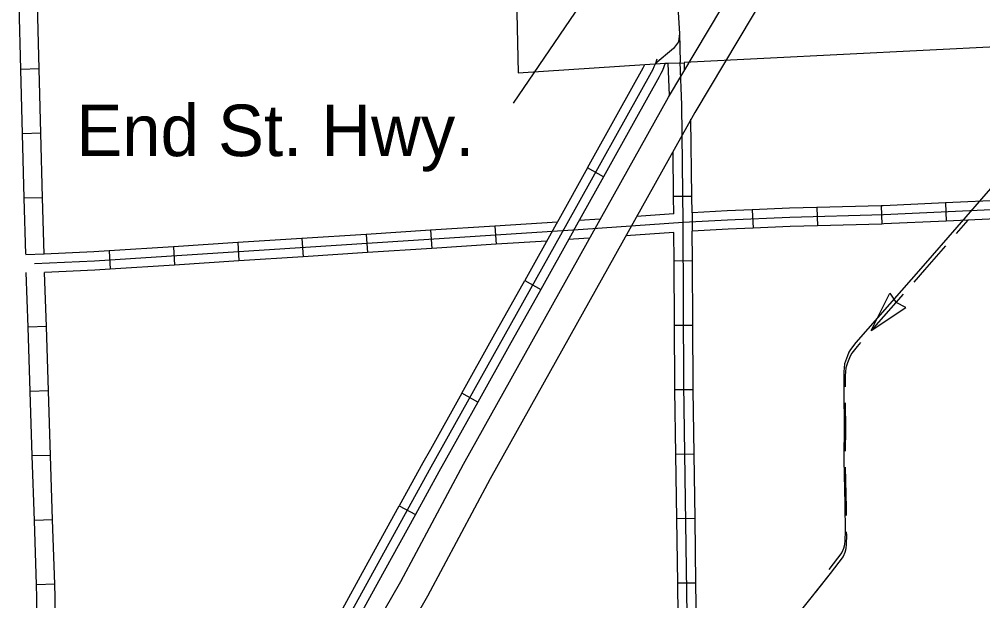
# Model space of a CAD drawing. Extents: x 1164457 to 1439835, y 1590918 to 1773502.
# Drawn here: x 1250867 to 1258762, y 1619648 to 1624411 of the extents above; entities that cross this region are included whole.
import ezdxf

# ---------------------------------------------------------------- set-up
doc = ezdxf.new("R2010")
doc.units = 0
for name, color, linetype in [('Level 15', 7, 'Continuous'), ('Level 31', 7, 'Continuous'), ('Level 32', 7, 'Continuous'), ('Level 33', 7, 'Continuous'), ('Level 34', 7, 'Continuous'), ('Level 41', 7, 'Continuous'), ('Level 43', 7, 'Continuous'), ('Level 6', 7, 'Continuous')]:
    doc.layers.add(name, color=color, linetype=linetype)

msp = doc.modelspace()

# ---------------------------------------------------------------- linework, layer by layer
at = {"layer": 'Level 15'}
for points in [[(1253993.2, 1619805.1), (1254506.1, 1620766.5), (1256186.5, 1623773.6), (1257379.6, 1625774), (1258934.5, 1628282.8), (1259494.9, 1629192.9), (1260659.4, 1631068)], [(1260872.2, 1630936.8), (1259707.6, 1629061.4), (1259147.2, 1628151.4), (1257593.2, 1625644.1), (1256403.1, 1623648.5), (1254725.5, 1620646.6), (1254211.9, 1619684)], [(1251163.5, 1614663.9), (1251218.9, 1614766.1), (1251254.2, 1614833.3), (1251300.8, 1614938.9), (1251428, 1615195.4), (1252210.7, 1616646.9), (1252911.7, 1617922.8), (1253993.2, 1619805.1)], [(1254211.9, 1619684), (1253129.6, 1617800.3), (1252430.3, 1616527.4), (1251647.9, 1615076.4), (1251506.8, 1614816.2), (1251450.7, 1614714.5), (1251414.8, 1614638.1), (1251385.8, 1614586.3), (1251323.1, 1614487.1), (1251311.8, 1614470.8)]]:
    msp.add_lwpolyline(points, dxfattribs=at)
at = {"layer": 'Level 31'}
for p, q in [((1255653.9, 1623120.3), (1255522.9, 1623193.2)), ((1255008.7, 1622270.9), (1255139.7, 1622197.8)), ((1254625, 1621275.7), (1254494, 1621348.9)), ((1254494, 1621348.9), (1254494, 1621348.9)), ((1253981, 1620425.4), (1254112.4, 1620353))]:
    msp.add_line(p, q, dxfattribs=at)
for points in [[(1256090, 1624084.8), (1256087.5, 1624075.1), (1256079, 1624048.3), (1256067.9, 1624021.3), (1256057.9, 1624000.3), (1256044.3, 1623975.8), (1255353.8, 1622735.2), (1254240.6, 1620741), (1252203.6, 1617045.1)], [(1255779.6, 1623654.6), (1255978.7, 1624012.2), (1255994.3, 1624040.3), (1256158.6, 1624051.1)], [(1256158.6, 1624051.1), (1256149.6, 1624022.7), (1256136.4, 1623990.8), (1256124.6, 1623965.9), (1256109.8, 1623939.4), (1255910.7, 1623581.6)], [(1255522.9, 1623193.2), (1255779.6, 1623654.6)], [(1255910.7, 1623581.6), (1255653.9, 1623120.3)], [(1255522.9, 1623193.2), (1255288.3, 1622771.7), (1255266.1, 1622732)], [(1255653.9, 1623120.3), (1255419.3, 1622698.7), (1255397.1, 1622658.8)], [(1255266.1, 1622732), (1255008.7, 1622270.9)], [(1255397.1, 1622658.8), (1255139.7, 1622197.8)], [(1254751.4, 1621809.9), (1255008.7, 1622270.9)], [(1255139.7, 1622197.8), (1254882.4, 1621736.8)], [(1254494, 1621348.9), (1254751.4, 1621809.9)], [(1254882.4, 1621736.8), (1254625, 1621275.7)], [(1254494, 1621348.9), (1254236.7, 1620887.8)], [(1254625, 1621275.7), (1254367.7, 1620814.7)], [(1254236.7, 1620887.8), (1254175.1, 1620777.4), (1253981, 1620425.4)], [(1254367.7, 1620814.7), (1254306.2, 1620704.7), (1254112.4, 1620353)], [(1253726.2, 1619963), (1253981, 1620425.4)], [(1254112.4, 1620353), (1253857.5, 1619890.6)], [(1253471.3, 1619500.5), (1253726.2, 1619963)], [(1253857.5, 1619890.6), (1253602.7, 1619428.1)]]:
    msp.add_lwpolyline(points, dxfattribs=at)
at = {"layer": 'Level 32'}
for p, q in [((1251030.5, 1624005), (1250880.5, 1624001.1)), ((1251044.2, 1623477.2), (1250894.2, 1623473.3)), ((1251057.9, 1622949.4), (1250907.9, 1622945.5)), ((1256378.7, 1622960.2), (1256228.8, 1622958.4)), ((1258456.4, 1622907.2), (1258463.2, 1622757.3)), ((1256380.3, 1622825.3), (1256381.7, 1622675.2)), ((1256873.7, 1622849.9), (1256880.2, 1622700.1)), ((1257402.5, 1622869.3), (1257406.6, 1622719.3)), ((1257930.3, 1622883.7), (1257934.4, 1622733.7)), ((1254237.4, 1622683.3), (1254247.1, 1622533.6)), ((1254764.3, 1622717.3), (1254774, 1622567.6)), ((1253183.6, 1622615.3), (1253193.3, 1622465.7)), ((1253710.5, 1622649.3), (1253720.2, 1622499.7)), ((1251602.9, 1622513.4), (1251612.6, 1622363.7)), ((1252129.8, 1622547.4), (1252139.5, 1622397.7)), ((1252656.7, 1622581.4), (1252666.4, 1622431.7)), ((1251069.9, 1622487.1), (1250919.9, 1622482.2)), ((1256383, 1622431.8), (1256233, 1622430.9)), ((1251088.8, 1621894.3), (1250938.9, 1621889.4)), ((1256386, 1621903.8), (1256236, 1621903)), ((1251106, 1621366.6), (1250956.1, 1621361.7)), ((1256389.3, 1621376.5), (1256239.3, 1621374.3)), ((1256396.9, 1620848.5), (1256246.9, 1620846.4)), ((1251123.2, 1620838.9), (1250973.3, 1620834)), ((1251140.4, 1620311.2), (1250990.5, 1620306.3)), ((1256404.5, 1620320.6), (1256254.5, 1620318.4)), ((1251157.6, 1619783.4), (1251007.7, 1619778.5)), ((1256412.1, 1619792.6), (1256262.2, 1619790.5))]:
    msp.add_line(p, q, dxfattribs=at)
for points in [[(1261295.4, 1630547.9), (1261306.2, 1630051), (1261324.9, 1629664.4), (1261348.7, 1628964), (1261365.2, 1628368), (1261458.8, 1624497.4), (1261503, 1623132.1), (1261505.5, 1623067.7), (1261501.7, 1623041.2), (1261495.4, 1623009.6), (1261481.5, 1622985.6), (1261466, 1622969.5), (1261449.4, 1622961.7), (1261391.9, 1622953.3), (1261142.6, 1622941.1), (1260938.5, 1622942), (1258950.1, 1622854.5), (1257949.9, 1622809.2), (1257180.1, 1622788.2), (1256671, 1622766), (1256306.3, 1622746.2), (1255487.8, 1622688.9), (1251482.4, 1622430.4), (1250992.3, 1622408.6)], [(1250880.5, 1624001.1), (1250866.8, 1624528.9)], [(1251030.5, 1624005), (1251016.8, 1624532.8)], [(1256194.7, 1623787.2), (1256184.5, 1624051.7), (1256316.7, 1624055.8)], [(1256372.7, 1617457.4), (1256353.6, 1618242.9), (1256357.3, 1618398.2), (1256313.6, 1621419), (1256306.3, 1622746.2), (1256294.8, 1623711), (1256281.4, 1624058.9)], [(1256317.4, 1623993), (1256316.7, 1624055.8)], [(1250894.2, 1623473.3), (1250880.5, 1624001.1)], [(1251044.2, 1623477.2), (1251030.5, 1624005)], [(1256378.7, 1622960.2), (1256371.2, 1623591.6)], [(1250907.9, 1622945.5), (1250894.2, 1623473.3)], [(1251057.9, 1622949.4), (1251044.2, 1623477.2)], [(1256228.8, 1622958.4), (1256224.3, 1623328.7)], [(1250919.8, 1622487), (1250907.9, 1622945.5)], [(1251069.9, 1622487.1), (1251057.9, 1622949.4)], [(1256230.4, 1622816.1), (1256228.8, 1622958.4)], [(1256380.3, 1622825.3), (1256378.7, 1622960.2)], [(1258456.4, 1622907.2), (1257947.1, 1622884.1), (1257930.3, 1622883.7)], [(1258984, 1622931), (1258946.7, 1622929.4), (1258456.4, 1622907.2)], [(1256873.7, 1622849.9), (1256667.3, 1622840.9), (1256380.3, 1622825.3)], [(1257402.5, 1622869.3), (1257177.4, 1622863.2), (1256873.7, 1622849.9)], [(1257930.3, 1622883.7), (1257402.5, 1622869.3)], [(1255276.4, 1622750.4), (1254764.3, 1622717.3)], [(1255627.9, 1622773.9), (1255454.4, 1622761.7)], [(1256230.4, 1622816.1), (1255925.9, 1622794.7)], [(1258463.2, 1622757.3), (1257952.6, 1622734.2), (1257934.4, 1622733.7)], [(1258876, 1622776), (1258463.2, 1622757.3)], [(1254237.4, 1622683.3), (1253710.5, 1622649.3)], [(1254764.3, 1622717.3), (1254237.4, 1622683.3)], [(1256231.7, 1622665.8), (1255838.5, 1622638.2)], [(1256233, 1622430.9), (1256231.7, 1622665.8)], [(1256880.2, 1622700.1), (1256674.7, 1622691.1), (1256381.7, 1622675.2)], [(1256383, 1622431.8), (1256381.7, 1622675.2)], [(1257406.6, 1622719.3), (1257182.7, 1622713.2), (1256880.2, 1622700.1)], [(1257934.4, 1622733.7), (1257406.6, 1622719.3)], [(1253183.6, 1622615.3), (1252656.7, 1622581.4)], [(1253710.5, 1622649.3), (1253183.6, 1622615.3)], [(1255189.3, 1622594.4), (1254774, 1622567.6)], [(1255540.4, 1622617.4), (1255492.9, 1622614), (1255367.5, 1622605.9)], [(1251602.9, 1622513.4), (1251478.3, 1622505.3), (1251069.9, 1622487.1)], [(1252129.8, 1622547.4), (1251602.9, 1622513.4)], [(1252656.7, 1622581.4), (1252129.8, 1622547.4)], [(1254247.1, 1622533.6), (1253720.2, 1622499.7)], [(1254774, 1622567.6), (1254247.1, 1622533.6)], [(1252666.4, 1622431.7), (1252139.5, 1622397.7)], [(1253193.3, 1622465.7), (1252666.4, 1622431.7)], [(1253720.2, 1622499.7), (1253193.3, 1622465.7)], [(1256236, 1621903), (1256233, 1622430.9)], [(1256386, 1621903.8), (1256383, 1622431.8)], [(1251612.6, 1622363.7), (1251486.4, 1622355.5), (1251074.3, 1622337.2)], [(1252139.5, 1622397.7), (1251612.6, 1622363.7)], [(1250938.9, 1621889.4), (1250924.3, 1622337)], [(1251088.8, 1621894.3), (1251074.3, 1622337.2)], [(1250956.1, 1621361.7), (1250938.9, 1621889.4)], [(1251106, 1621366.6), (1251088.8, 1621894.3)], [(1256239.3, 1621374.3), (1256238.7, 1621418.3), (1256236, 1621903)], [(1256389.3, 1621376.5), (1256388.6, 1621419.8), (1256386, 1621903.8)], [(1250973.3, 1620834), (1250956.1, 1621361.7)], [(1251123.2, 1620838.9), (1251106, 1621366.6)], [(1256246.9, 1620846.4), (1256239.3, 1621374.3)], [(1256396.9, 1620848.5), (1256389.3, 1621376.5)], [(1256404.5, 1620320.6), (1256396.9, 1620848.5)], [(1250990.5, 1620306.3), (1250973.3, 1620834)], [(1251140.4, 1620311.2), (1251123.2, 1620838.9)], [(1256254.5, 1620318.4), (1256246.9, 1620846.4)], [(1251007.7, 1619778.5), (1250990.5, 1620306.3)], [(1251157.6, 1619783.4), (1251140.4, 1620311.2)], [(1256262.2, 1619790.5), (1256254.5, 1620318.4)], [(1256412.1, 1619792.6), (1256404.5, 1620320.6)], [(1251016, 1619252.2), (1251011.1, 1619673.1), (1251007.7, 1619778.5)], [(1251166, 1619254), (1251161.1, 1619676.4), (1251157.6, 1619783.4)], [(1256269.8, 1619262.5), (1256262.2, 1619790.5)], [(1256419.8, 1619264.7), (1256412.1, 1619792.6)]]:
    msp.add_lwpolyline(points, dxfattribs=at)
at = {"layer": 'Level 33'}
msp.add_lwpolyline([(1256249.2, 1625531.3), (1256250.8, 1625366.7), (1256266.7, 1624465.9), (1256276.2, 1624293.7), (1256270, 1624226.9), (1256227.3, 1624172.2), (1256076.4, 1624045.7)], dxfattribs=at)
at = {"layer": 'Level 34'}
msp.add_lwpolyline([(1256276.2, 1624293.7), (1256281.4, 1624058.9)], dxfattribs=at)
at = {"layer": 'Level 41'}
msp.add_line((1255945.6, 1625241.9), (1254915.3, 1623723.7), dxfattribs=at)
at = {"layer": 'Level 43'}
for p, q in [((1257847.2, 1621861.2), (1257999.6, 1622168.7)), ((1257999.6, 1622168.7), (1258050.3, 1622092.7)), ((1257847.2, 1621861.2), (1258133, 1622051.3)), ((1258133, 1622051.3), (1258051.2, 1622091.9))]:
    msp.add_line(p, q, dxfattribs=at)
for points in [[(1258825.4, 1623023.6), (1258273.8, 1622390.2), (1257722.1, 1621763.8), (1257679, 1621707.1), (1257665.4, 1621683.6), (1257653.5, 1621655.4), (1257629.7, 1621589), (1257624.8, 1621522.4), (1257623.5, 1621348.5), (1257626, 1621089.5), (1257624.1, 1620803.1), (1257630.9, 1620440.2), (1257633.4, 1620216.1), (1257631.5, 1620142.8), (1257628.5, 1620105.8), (1257621.7, 1620074.9), (1257606.3, 1620043.5), (1257500, 1619903.6)], [(1258639.4, 1622765.3), (1258543.5, 1622655.2)], [(1258456.8, 1622555.7), (1258284.5, 1622357.9), (1258196.2, 1622257.5)], [(1258108.9, 1622158.4), (1257847.2, 1621861.2)], [(1257760, 1621762.2), (1257732.9, 1621731.4), (1257689.8, 1621674.7), (1257676.2, 1621651.3), (1257664.3, 1621623.1), (1257654.8, 1621596.6)], [(1257654.8, 1621596.6), (1257640.5, 1621556.6), (1257635.5, 1621490), (1257634.9, 1621401.3)], [(1257634.8, 1621269.3), (1257636.8, 1621057.2), (1257635.6, 1620873.3)], [(1257635.5, 1620741.4), (1257641.7, 1620407.9), (1257642.4, 1620345.4)], [(1257643.8, 1620213.4), (1257644.2, 1620183.8), (1257642.3, 1620110.4), (1257639.2, 1620073.4), (1257632.5, 1620042.6), (1257617.1, 1620011.1), (1257510.7, 1619871.3)], [(1257510.7, 1619871.3), (1257247.9, 1619536.4), (1256357.3, 1618398.2), (1256319.1, 1618363.7), (1256185.9, 1618180), (1255879, 1617808.8), (1253428.3, 1614626), (1253305.2, 1614470.8)], [(1257510.7, 1619871.3), (1257388.5, 1619715.5)]]:
    msp.add_lwpolyline(points, dxfattribs=at)
at = {"layer": 'Level 6'}
for points in [[(1256316.6, 1624060.7), (1258926.4, 1624190.1), (1258913.1, 1625540.6), (1258770.1, 1628119.8)], [(1254928.5, 1625201.7), (1254956.3, 1623971.7), (1255994.3, 1624040.3)], [(1256158.6, 1624051.1), (1256184.5, 1624052.8)]]:
    msp.add_lwpolyline(points, dxfattribs=at)

# ---------------------------------------------------------------- texts
at = {"layer": 'Level 41'}
msp.add_text('End St. Hwy.', height=421.999, dxfattribs=at).set_placement((1251334.6, 1623290))

doc.saveas('drawing.dxf')
